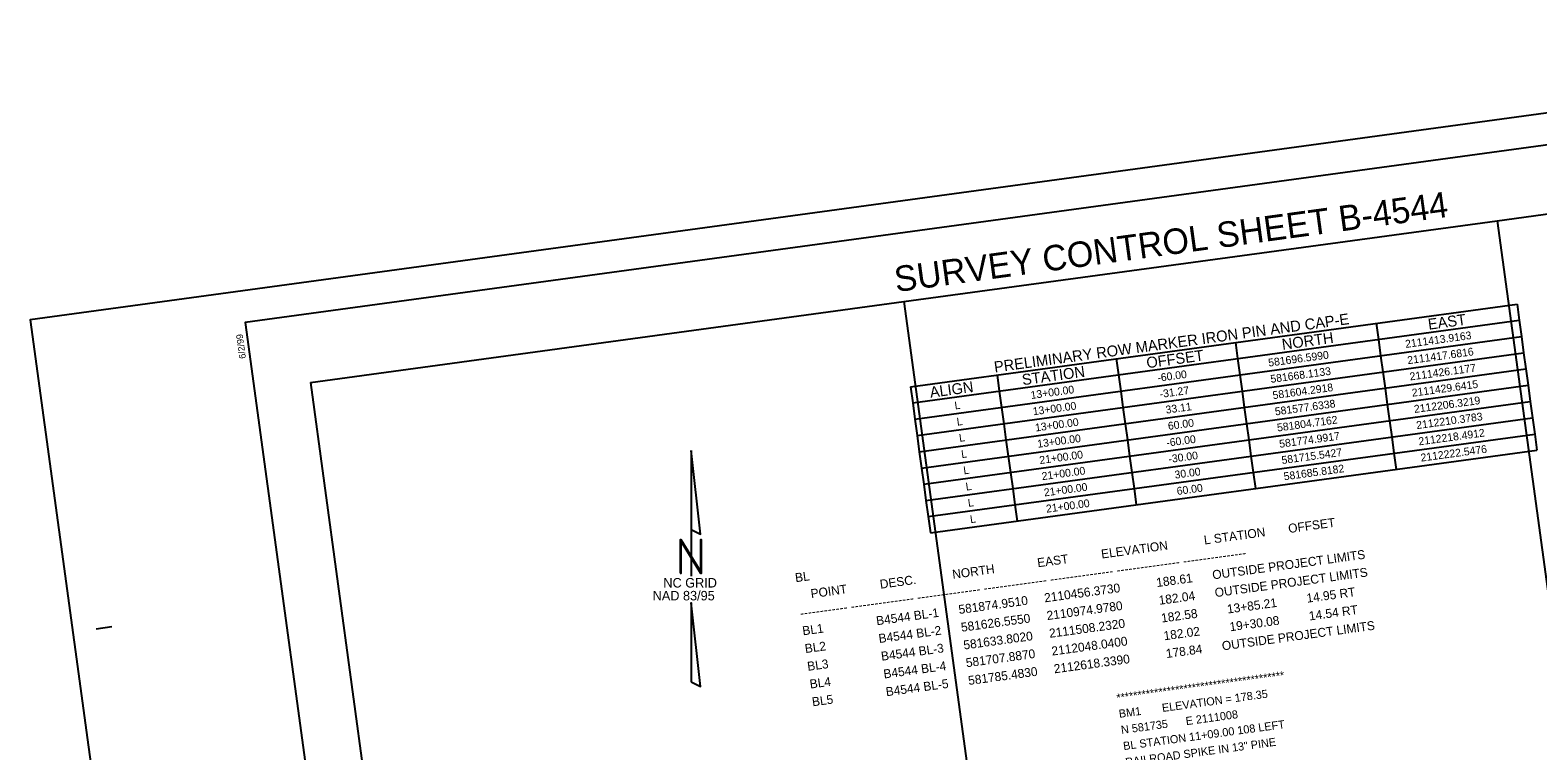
# Model space of a CAD drawing. Extents: x 2110875 to 2112582, y 581169 to 582406.
# Drawn here: x 2110875 to 2111987, y 581874 to 582406 of the extents above; entities that cross this region are included whole.
import ezdxf

# ---------------------------------------------------------------- set-up
doc = ezdxf.new("R2010")
doc.units = 0
for name, color, linetype in [('CTL North Arrow NAD 83 95 CELL', 7, 'Continuous'), ('CTL Sheet Border CELL', 7, 'Continuous'), ('CTL Sheet Notes CELL', 7, 'Continuous'), ('CTL Sheet Table Cell', 7, 'Continuous'), ('CTL Sheet Text', 7, 'Continuous'), ('Scratch_Level_3', 7, 'Continuous'), ('Sheet Plot Border Outside CELL', 7, 'Continuous')]:
    doc.layers.add(name, color=color, linetype=linetype)

msp = doc.modelspace()

# ---------------------------------------------------------------- linework, layer by layer
at = {"layer": 'CTL North Arrow NAD 83 95 CELL'}
for points in [[(2111363, 582095.9), (2111363, 582037.5), (2111369.9, 582034.1)], [(2111354.8, 582005.3), (2111355.5, 582005.3), (2111355.5, 582028.6), (2111369.9, 582005.3), (2111370.6, 582005.3), (2111370.6, 582030), (2111369.9, 582030), (2111369.9, 582006.7), (2111355.5, 582030), (2111354.8, 582030)], [(2111363, 581925), (2111369.9, 581921.6), (2111363, 581983.3)]]:
    msp.add_lwpolyline(points, close=True, dxfattribs=at)
msp.add_lwpolyline([(2111363, 582037.5), (2111363, 582003.2)], dxfattribs=at)
at = {"layer": 'CTL Sheet Border CELL'}
msp.add_line((2110923.9, 581964.3), (2110935.6, 581965.9), dxfattribs=at)
msp.add_lwpolyline([(2112429.6, 582380.6), (2111033.9, 582190.2), (2111167.2, 581213.1), (2112563, 581403.6)], close=True, dxfattribs=at)
at = {"layer": 'CTL Sheet Table Cell'}
for p, q in [((2111524.7, 582142.9), (2111972.1, 582203.9)), ((2111972.1, 582203.9), (2111973.8, 582191.9)), ((2111526.3, 582130.9), (2111973.8, 582191.9)), ((2111868.3, 582189.7), (2111869.9, 582177.8)), ((2111973.8, 582191.9), (2111975.4, 582179.9)), ((2111528, 582118.9), (2111975.4, 582179.9)), ((2111869.9, 582177.8), (2111871.5, 582165.8)), ((2111975.4, 582179.9), (2111977, 582168)), ((2111529.6, 582106.9), (2111977, 582168)), ((2111764.4, 582175.6), (2111766, 582163.6)), ((2111977, 582168), (2111978.7, 582156)), ((2111531.2, 582094.9), (2111978.7, 582156)), ((2111676.5, 582163.6), (2111678.1, 582151.6)), ((2111766, 582163.6), (2111767.7, 582151.6)), ((2111871.5, 582165.8), (2111873.2, 582153.8)), ((2111978.7, 582156), (2111980.3, 582144)), ((2111588.6, 582151.6), (2111590.2, 582139.6)), ((2111678.1, 582151.6), (2111679.8, 582139.6)), ((2111767.7, 582151.6), (2111769.3, 582139.6)), ((2111873.2, 582153.8), (2111874.8, 582141.8)), ((2111524.7, 582142.9), (2111526.3, 582130.9)), ((2111532.9, 582082.9), (2111980.3, 582144)), ((2111590.2, 582139.6), (2111591.9, 582127.6)), ((2111679.8, 582139.6), (2111681.4, 582127.6)), ((2111769.3, 582139.6), (2111770.9, 582127.6)), ((2111874.8, 582141.8), (2111876.4, 582129.8)), ((2111980.3, 582144), (2111981.9, 582132)), ((2111526.3, 582130.9), (2111528, 582118.9)), ((2111534.5, 582070.9), (2111981.9, 582132)), ((2111591.9, 582127.6), (2111593.5, 582115.6)), ((2111681.4, 582127.6), (2111683, 582115.6)), ((2111770.9, 582127.6), (2111772.6, 582115.6)), ((2111876.4, 582129.8), (2111878.1, 582117.8)), ((2111981.9, 582132), (2111983.6, 582120)), ((2111528, 582118.9), (2111529.6, 582106.9)), ((2111536.1, 582059), (2111983.6, 582120)), ((2111593.5, 582115.6), (2111595.1, 582103.6)), ((2111683, 582115.6), (2111684.7, 582103.6)), ((2111772.6, 582115.6), (2111774.2, 582103.7)), ((2111878.1, 582117.8), (2111879.7, 582105.8)), ((2111983.6, 582120), (2111985.2, 582108)), ((2111529.6, 582106.9), (2111531.2, 582094.9)), ((2111537.8, 582047), (2111985.2, 582108)), ((2111595.1, 582103.6), (2111596.8, 582091.7)), ((2111684.7, 582103.6), (2111686.3, 582091.7)), ((2111774.2, 582103.7), (2111775.8, 582091.7)), ((2111879.7, 582105.8), (2111881.3, 582093.9)), ((2111985.2, 582108), (2111986.8, 582096)), ((2111531.2, 582094.9), (2111532.9, 582082.9)), ((2111539.4, 582035), (2111986.8, 582096)), ((2111596.8, 582091.7), (2111598.4, 582079.7)), ((2111686.3, 582091.7), (2111687.9, 582079.7)), ((2111775.8, 582091.7), (2111777.5, 582079.7)), ((2111881.3, 582093.9), (2111883, 582081.9)), ((2111532.9, 582082.9), (2111534.5, 582070.9)), ((2111598.4, 582079.7), (2111600.1, 582067.7)), ((2111687.9, 582079.7), (2111689.6, 582067.7)), ((2111777.5, 582079.7), (2111779.1, 582067.7)), ((2111534.5, 582070.9), (2111536.1, 582059)), ((2111600.1, 582067.7), (2111601.7, 582055.7)), ((2111689.6, 582067.7), (2111691.2, 582055.7)), ((2111536.1, 582059), (2111537.8, 582047)), ((2111601.7, 582055.7), (2111603.3, 582043.7)), ((2111537.8, 582047), (2111539.4, 582035))]:
    msp.add_line(p, q, dxfattribs=at)
at = {"layer": 'Scratch_Level_3'}
for p, q in [((2111957.4, 582265.4), (2112395.1, 582325.1)), ((2111519.7, 582205.7), (2111957.4, 582265.4)), ((2111957.4, 582265.4), (2112055.8, 581544.5)), ((2111082, 582145.9), (2111519.7, 582205.7)), ((2111519.7, 582205.7), (2111618.1, 581484.8)), ((2111082, 582145.9), (2111180.4, 581425))]:
    msp.add_line(p, q, dxfattribs=at)
at = {"layer": 'Sheet Plot Border Outside CELL'}
msp.add_lwpolyline([(2111015, 581168.7), (2112582, 581382.5), (2112442.3, 582406.1), (2110875.3, 582192.2)], close=True, dxfattribs=at)

# ---------------------------------------------------------------- texts
at = {"layer": 'CTL North Arrow NAD 83 95 CELL'}
for s, p in [('NC GRID', (2111342.4, 581994.7)), ('NAD 83/95', (2111334.5, 581985.2))]:
    msp.add_text(s, height=7, dxfattribs=at).set_placement(p)
at = {"layer": 'CTL Sheet Border CELL'}
for s, height, rotation, p in [('SURVEY CONTROL SHEET B-4544', 18.783, 7.771, (2111514.1, 582212.7)), ('6/2/99', 4.93, 97.771, (2111034.5, 582163.9))]:
    msp.add_text(s, height=height, rotation=rotation, dxfattribs=at).set_placement(p)
at = {"layer": 'CTL Sheet Notes CELL'}
for s, height, p in [('PRELIMINARY ROW MARKER IRON PIN AND CAP-E', 8.064, (2111586.9, 582153.4)), ('EAST', 8.06, (2111907, 582184.9)), ('NORTH', 8.06, (2111799.2, 582170.1)), ('OFFSET', 8.06, (2111699.3, 582156.5)), ('STATION', 8.06, (2111607.5, 582144)), ('ALIGN', 8.06, (2111539.5, 582134.7))]:
    msp.add_text(s, height=height, rotation=7.771, dxfattribs=at).set_placement(p)
at = {"layer": 'CTL Sheet Text'}
for s, height, p in [('2111413.9163', 5.76, (2111890, 582171.5)), ('581696.5990', 5.76, (2111789, 582157.7)), ('2111417.6816', 5.76, (2111891.6, 582159.5)), ('581668.1133', 5.76, (2111790.6, 582145.7)), ('2111426.1177', 5.76, (2111893.3, 582147.5)), ('-60.00', 5.76, (2111707.2, 582146.5)), ('581604.2918', 5.76, (2111792.2, 582133.7)), ('2111429.6415', 5.76, (2111894.9, 582135.5)), ('13+00.00', 5.76, (2111613.7, 582133.8)), ('-31.27', 5.76, (2111708.9, 582134.6)), ('581577.6338', 5.76, (2111793.9, 582121.7)), ('2112206.3219', 5.76, (2111896.5, 582123.5)), ('L', 5.76, (2111557.6, 582126.1)), ('13+00.00', 5.76, (2111615.3, 582121.8)), ('33.11', 5.76, (2111713.3, 582123)), ('2112210.3783', 5.76, (2111898.2, 582111.6)), ('L', 5.76, (2111559.2, 582114.1)), ('13+00.00', 5.76, (2111617, 582109.8)), ('60.00', 5.76, (2111715, 582111)), ('581804.7162', 5.76, (2111795.5, 582109.8)), ('2112218.4912', 5.76, (2111899.8, 582099.6)), ('L', 5.76, (2111560.9, 582102.2)), ('13+00.00', 5.76, (2111618.6, 582097.8)), ('-60.00', 5.76, (2111713.8, 582098.6)), ('581774.9917', 5.76, (2111797.1, 582097.8)), ('2112222.5476', 5.76, (2111901.4, 582087.6)), ('L', 5.76, (2111562.5, 582090.2)), ('21+00.00', 5.76, (2111620.2, 582085.8)), ('-30.00', 5.76, (2111715.4, 582086.6)), ('581715.5427', 5.76, (2111798.8, 582085.8)), ('L', 5.76, (2111564.1, 582078.2)), ('21+00.00', 5.76, (2111621.9, 582073.9)), ('30.00', 5.76, (2111719.9, 582075)), ('581685.8182', 5.76, (2111800.4, 582073.8)), ('L', 5.76, (2111565.8, 582066.2)), ('21+00.00', 5.76, (2111623.5, 582061.9)), ('60.00', 5.76, (2111721.5, 582063)), ('L', 5.76, (2111567.4, 582054.2)), ('21+00.00', 5.76, (2111625.1, 582049.9)), ('    POINT          DESC.           NORTH             EAST          ELEVATION           L STATION       OFFSET', 6.6, (2111441.8, 581985.5)), ('L', 5.76, (2111569, 582042.2)), ('BL1                B4544 BL-1      581874.9510     2110456.3730           188.61      OUTSIDE PROJECT LIMITS                 ', 6.6, (2111445.4, 581959.4)), ('------------ ---------------- ---------------- ---------------- ---------------- ---------------- ----------------', 6.6, (2111443.6, 581972.4)), ('BL', 6.6, (2111440, 581998.6)), ('BL2                B4544 BL-2      581626.5550     2110974.9780           182.04      OUTSIDE PROJECT LIMITS                 ', 6.6, (2111447.2, 581946.3)), ('BL3                B4544 BL-3      581633.8020     2111508.2320           182.58         13+85.21         14.95 RT', 6.6, (2111449, 581933.2)), ('BL4                B4544 BL-4      581707.8870     2112048.0400           182.02         19+30.08         14.54 RT', 6.6, (2111450.8, 581920.1)), ('BL5                B4544 BL-5      581785.4830     2112618.3390           178.84      OUTSIDE PROJECT LIMITS                 ', 6.6, (2111452.5, 581907)), ('****************************************', 6, (2111677.1, 581910.3)), ('BM1       ELEVATION = 178.35', 6, (2111678.8, 581898.5)), ('N 581735      E 2111008', 6, (2111680.4, 581886.6)), ('BL STATION 11+09.00 108 LEFT', 6, (2111682, 581874.7)), ('RAILROAD SPIKE IN 13" PINE', 6, (2111683.6, 581862.8))]:
    msp.add_text(s, height=height, rotation=7.771, dxfattribs=at).set_placement(p)

doc.saveas('drawing.dxf')
